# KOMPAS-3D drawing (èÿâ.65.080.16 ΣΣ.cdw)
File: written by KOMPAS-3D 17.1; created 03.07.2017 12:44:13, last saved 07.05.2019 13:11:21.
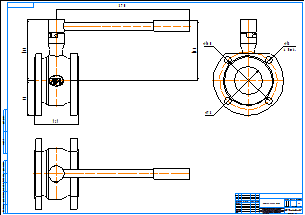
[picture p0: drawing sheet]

Sheet 1: A1, landscape

Title block, sheet 1: name: КШГ.65.080.16 фф; material: Внимание! Данный продукт является объектом авторского права ООО «Торговый Дом АДЛ». / Запрещается изменение, копирование, распространение / (в том числе путем копирования на другие сайты и ресурсы в Интернете) / или любое иное использование информации и объектов без предварительного / согласия правообладателя (ООО «Торговый Дом АДЛ»).; sheets: 1; organisation: ООО "Торговый дом АДЛ"; sheet format: A1; stored path: C:\Users\kka\KOMPAS_Work\!Trash\СС02 СС03 ФФ Смотровые стекла\СС01.cdw

Views: Спереди 1, Проекционный вид 2, Проекционный вид 3
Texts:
  Klimkovich
  ADL
Dimensions and other numbers on the sheet: 370; 166; 121; 98; 169; 160; 78; 18; 4 Отв.; 1:1; 1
